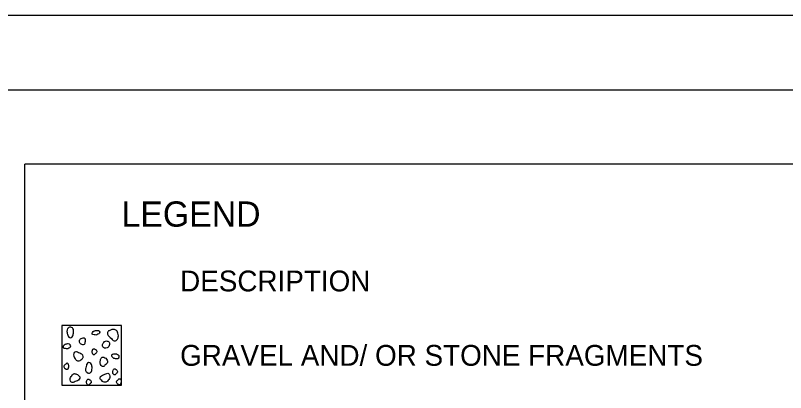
# Model space of a CAD drawing. Extents: x -59 to 43, y 0 to 22.
# Drawn here: x 11.6 to 16.78, y 19.46 to 22 of the extents above; entities that cross this region are included whole.
import ezdxf

# ---------------------------------------------------------------- set-up
doc = ezdxf.new("R2010")
doc.units = 0
for name, color, linetype in [('Default', 7, 'Continuous'), ('SH_Border', 7, 'Continuous'), ('SH_Cut_Line', 7, 'Continuous'), ('SH_Data', 7, 'Continuous'), ('SH_Text', 7, 'Continuous')]:
    doc.layers.add(name, color=color, linetype=linetype)

msp = doc.modelspace()

# ---------------------------------------------------------------- linework, layer by layer
at = {"layer": 'Default'}
for p, q in [((11.9167, 19.915), (11.9167, 19.915)), ((12.3167, 19.915), (12.3167, 19.915)), ((12.0815, 19.6498), (12.0776, 19.6323)), ((11.9167, 19.515), (11.9167, 19.515)), ((12.3167, 19.515), (12.3167, 19.515))]:
    msp.add_line(p, q, dxfattribs=at)
for points in [[(11.9563, 19.8505), (11.9506, 19.8759), (11.9552, 19.8954), (11.9713, 19.9046), (11.9908, 19.8954), (11.9943, 19.8644), (11.9863, 19.8402), (11.9713, 19.8333), (11.9587, 19.8448), (11.9563, 19.8505)], [(12.2899, 19.8716), (12.296, 19.8391), (12.2867, 19.8188), (12.2767, 19.812), (12.2619, 19.8155), (12.2493, 19.8276), (12.2242, 19.8576), (12.2272, 19.8763), (12.2355, 19.8809), (12.2515, 19.8884), (12.267, 19.8894), (12.2756, 19.8872), (12.2839, 19.8814), (12.2899, 19.8716)], [(12.1583, 19.8566), (12.1703, 19.8638), (12.1681, 19.8769), (12.1541, 19.8831), (12.1333, 19.879), (12.1214, 19.8686), (12.1192, 19.8586), (12.1333, 19.854), (12.1453, 19.8519), (12.1583, 19.8566)], [(11.9631, 19.765), (11.9751, 19.7723), (11.973, 19.7853), (11.959, 19.7916), (11.9382, 19.7874), (11.9262, 19.777), (11.9242, 19.7671), (11.9382, 19.7624), (11.9501, 19.7603), (11.9627, 19.765)], [(12.0747, 19.8103), (12.0685, 19.7895), (12.0404, 19.7947), (12.0321, 19.8114), (12.0435, 19.8259), (12.0571, 19.8301), (12.0737, 19.827), (12.0747, 19.8103)], [(12.1976, 19.8022), (12.1887, 19.7837), (12.2027, 19.7638), (12.2203, 19.7646), (12.2365, 19.7881), (12.2306, 19.8073), (12.2108, 19.811), (12.1976, 19.8022)], [(12.0099, 19.6867), (11.9959, 19.7103), (11.9974, 19.7287), (12.0033, 19.7368), (12.0158, 19.7383), (12.029, 19.7324), (12.057, 19.7162), (12.0599, 19.7008), (12.0548, 19.6949), (12.0445, 19.6845), (12.0327, 19.6794), (12.0253, 19.6786), (12.0173, 19.6808), (12.0099, 19.6867)], [(12.1397, 19.725), (12.1517, 19.7385), (12.1433, 19.7552), (12.1287, 19.7594), (12.1215, 19.75), (12.1199, 19.7349), (12.1241, 19.7234), (12.1293, 19.7192), (12.1355, 19.7203), (12.1397, 19.725)], [(12.2053, 19.6484), (12.224, 19.6695), (12.211, 19.6955), (12.1882, 19.7021), (12.1769, 19.6874), (12.1744, 19.6638), (12.181, 19.6459), (12.1891, 19.6395), (12.1988, 19.641), (12.2053, 19.6484)], [(12.2897, 19.7196), (12.3017, 19.7123), (12.2996, 19.6993), (12.2856, 19.693), (12.2647, 19.6972), (12.2528, 19.7076), (12.2507, 19.7175), (12.2647, 19.7222), (12.2767, 19.7242), (12.2897, 19.7196)], [(11.9425, 19.6556), (11.9305, 19.6425), (11.9389, 19.6259), (11.9535, 19.6217), (11.9607, 19.6311), (11.9623, 19.6461), (11.9581, 19.6576), (11.9529, 19.6618), (11.9467, 19.6607), (11.9425, 19.656)], [(12.0776, 19.6323), (12.0758, 19.6244), (12.0804, 19.6049), (12.0965, 19.5957), (12.116, 19.6049), (12.1166, 19.6056)], [(12.1166, 19.6056), (12.1195, 19.6359), (12.1114, 19.6601), (12.0965, 19.667), (12.0838, 19.6555), (12.0815, 19.6498)], [(11.9867, 19.584), (11.9728, 19.5605), (11.9742, 19.5421), (11.9801, 19.534), (11.9926, 19.5325), (12.0059, 19.5384), (12.0338, 19.5546), (12.0367, 19.5701), (12.0316, 19.5759), (12.0213, 19.5862), (12.0096, 19.5914), (12.0022, 19.5921), (11.9941, 19.5899), (11.9867, 19.584)], [(12.224, 19.5427), (12.238, 19.5662), (12.2365, 19.5846), (12.2306, 19.5927), (12.2182, 19.5942), (12.2048, 19.5883), (12.1769, 19.5721), (12.174, 19.5567), (12.1791, 19.5508), (12.1894, 19.5405), (12.2012, 19.5353), (12.2085, 19.5345), (12.2167, 19.5367), (12.224, 19.5427)], [(12.2786, 19.5895), (12.2905, 19.603), (12.2822, 19.6197), (12.2676, 19.6239), (12.2604, 19.6145), (12.2588, 19.5994), (12.263, 19.5879), (12.2682, 19.5837), (12.2744, 19.5849), (12.2786, 19.5895)], [(12.1018, 19.521), (12.1138, 19.5346), (12.1054, 19.5513), (12.0908, 19.5554), (12.0836, 19.5461), (12.082, 19.531), (12.0862, 19.5195), (12.0914, 19.5153), (12.0976, 19.5164), (12.1018, 19.521)], [(12.2957, 19.5524), (12.2837, 19.5389), (12.2921, 19.5222), (12.3066, 19.518), (12.3139, 19.5275), (12.3154, 19.5425), (12.3113, 19.554), (12.3061, 19.5582), (12.2999, 19.5571), (12.2957, 19.5524)]]:
    msp.add_spline(points, degree=3, dxfattribs=at)
at = {"layer": 'SH_Border'}
msp.add_lwpolyline([(1.5, 21.5), (33.5, 21.5), (33.5, 0.5), (1.5, 0.5)], close=True, dxfattribs=at)
at = {"layer": 'SH_Cut_Line'}
msp.add_lwpolyline([(0, 0), (34, 0), (34, 22), (0, 22)], close=True, dxfattribs=at)
at = {"layer": 'SH_Data'}
for p in [(11.6667, 5.18), (21.8333, 21)]:
    msp.add_line(p, (11.6667, 21), dxfattribs=at)
msp.add_lwpolyline([(11.9167, 19.515), (12.3167, 19.515), (12.3167, 19.915), (11.9167, 19.915)], close=True, dxfattribs=at)

# ---------------------------------------------------------------- texts
at = {"layer": 'SH_Text'}
for s, height, p in [('LEGEND', 0.17, (12.3177, 20.58)), ('DESCRIPTION', 0.14, (12.7116, 20.145)), ('GRAVEL AND/ OR STONE FRAGMENTS', 0.14, (12.7116, 19.645))]:
    msp.add_text(s, height=height, dxfattribs=at).set_placement(p)

doc.saveas('drawing.dxf')
